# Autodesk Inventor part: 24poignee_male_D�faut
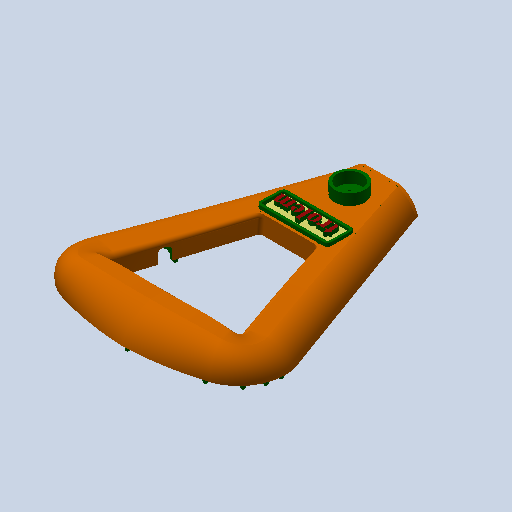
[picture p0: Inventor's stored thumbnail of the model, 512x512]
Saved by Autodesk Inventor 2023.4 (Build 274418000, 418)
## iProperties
Created: 2011-01
Part Number: 24poignee_male_D�faut
Document SubType Name: Modeling
Designer: eric
Density: 1 g/cm^3
Mass: 69.2638 g
Surface Area: 653.149 cm^2
Volume: 69.2638 cm^3
Material: Générique
Appearance: 0,128,0
Author: eric
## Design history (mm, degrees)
feature "Base1"
node "Corps solides"
node "Corps surfaciques"
node "Solide1"
